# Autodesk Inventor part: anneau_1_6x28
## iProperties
Created: 2011-01
Part Number: anneau_1_6x28
Document SubType Name: Modeling
Designer: eric
Density: 1 g/cm^3
Mass: 0.176863 g
Surface Area: 4.42158 cm^2
Volume: 0.176863 cm^3
Author: eric
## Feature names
1. Base1
